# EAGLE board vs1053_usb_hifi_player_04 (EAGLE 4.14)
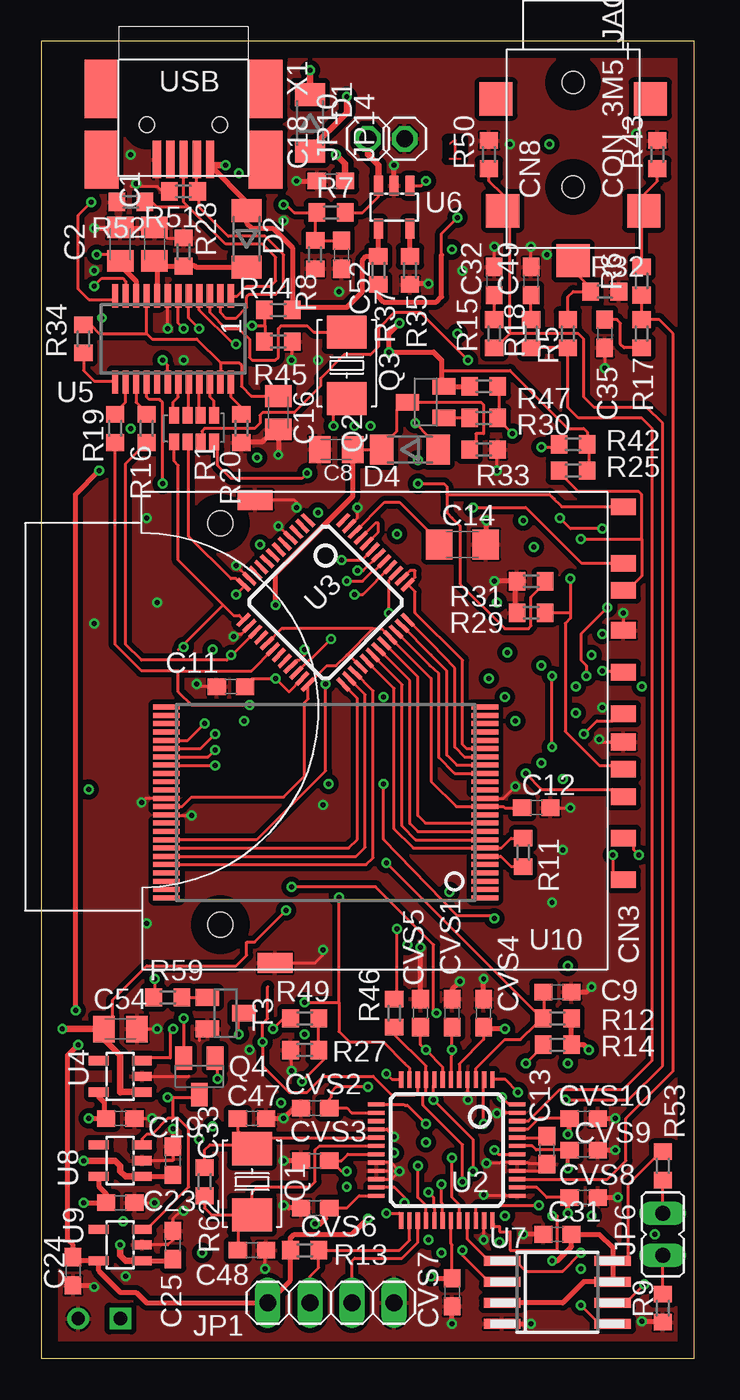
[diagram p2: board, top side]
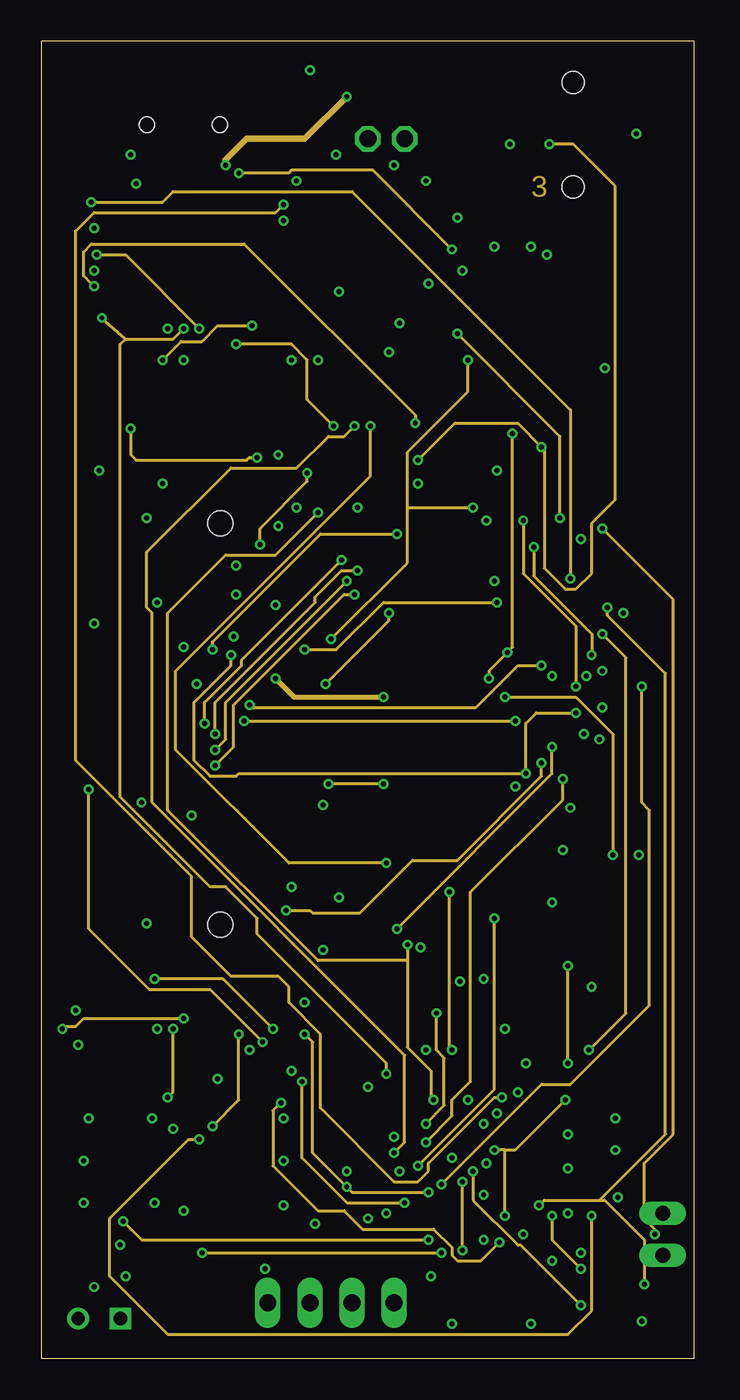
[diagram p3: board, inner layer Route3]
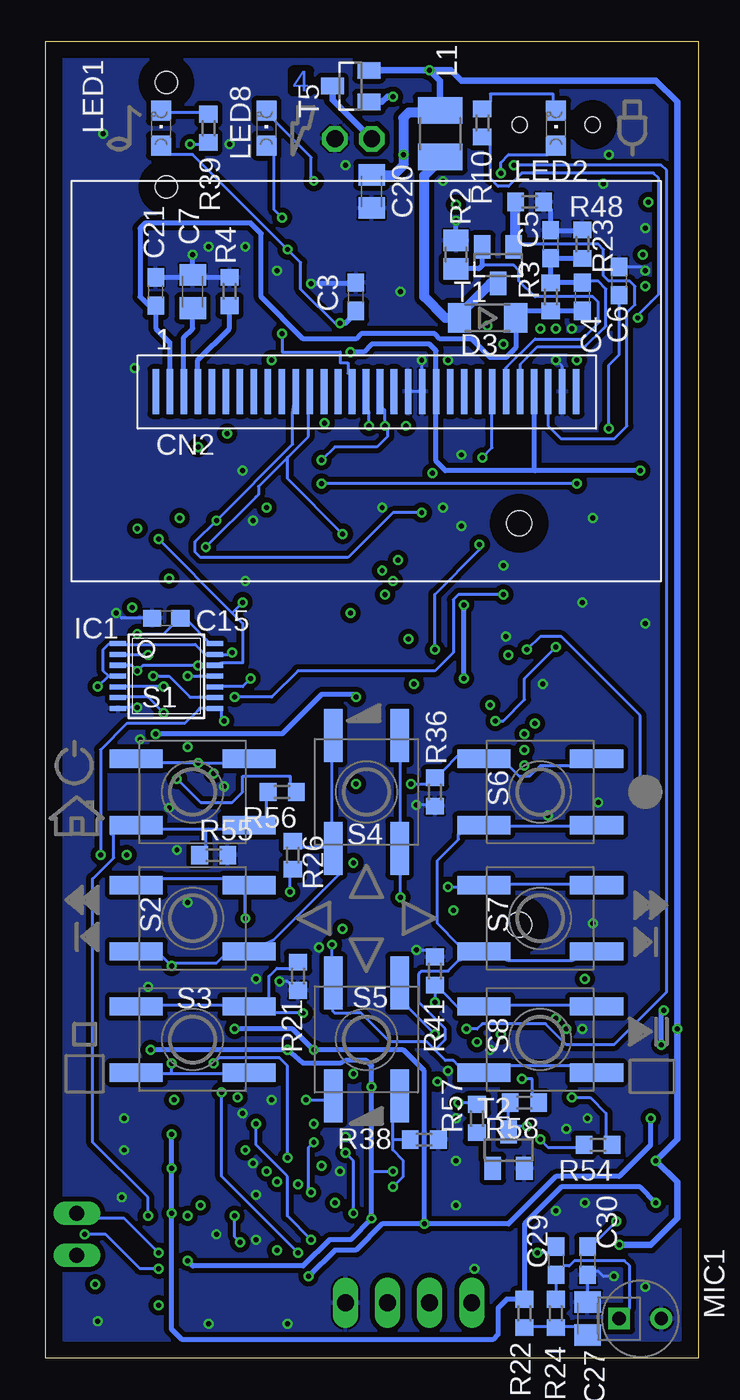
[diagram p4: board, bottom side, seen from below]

Size 39.35 x 79.36 mm. Coordinates in mm from the lower left corner, seen from the top.
Outline: 0,0 39.35,0 39.35,79.36 0,79.36 0,0
Copper layers (1*2+3*16): Top 0.0356mm / dielectric 1.5011mm / $GND 0.0356mm / dielectric 0.1499mm / Route3 0.0356mm / dielectric 0.2007mm / Bottom 0.0356mm
Design rules "oma_4layer": minimum track width 7mil, minimum drill 0.3mm, track to track 0.15mm, track to pad 8mil, pad to pad 7mil, via to via 8mil, smd to smd 7mil, copper to edge 40mil, drill to drill 8mil, minimum pad ring 10mil, minimum via ring 0.15mm, stop-mask expansion 0.1mm, vias tented up to drill 100mil, thermal gap 5mil

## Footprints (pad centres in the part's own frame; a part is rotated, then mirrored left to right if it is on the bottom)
C0805K = smd 1.3 x 1.6: 1 -1,0; 2 1,0
C0603 = smd 1.1 x 1: 1 -0.85,0; 2 0.85,0
C1206 = smd 1.6 x 1.8: 1 -1.4,0; 2 1.4,0
CON_DESITRON_OLED = smd 0.4 x 2.7: 1 0,0; 2 0.845,0; 3 1.69,0; 4 2.535,0; 5 3.38,0; 6 4.225,0; 7 5.07,0; 8 5.915,0; 9 6.76,0; 10 7.605,0; 11 8.45,0; 12 9.295,0; 13 10.14,0; 14 10.985,0; 15 11.83,0; 16 12.675,0; 17 13.52,0; 18 14.365,0; 19 15.21,0; 20 16.055,0; 21 16.9,0; 22 17.745,0; 23 18.59,0; 24 19.435,0; 25 20.28,0; 26 21.125,0; 27 21.97,0; 28 22.815,0; 29 23.66,0; 30 24.505,0; 31 25.35,0
CON_SDCARD_PROCONN = smd 1.5 x 1: 1 -24.3,21.48; 2 -24.3,18.98; 3 -24.3,16.48; 4 -24.3,14.83; 5 -24.3,13.18; 6 -24.3,11.48; 7 -24.3,8.98; 8 -24.3,6.45; 9 -24.3,4.05; 10 -24.3,2.4; 11 -24.3,-1 | smd 2.1 x 1.2: 12 -2.1,-1.4; 13 -3.3,26.51 | hole 1.5: 0,0; 0,24.2
CON_3M5_JACK_SMD = smd 2 x 2: P$1 -4.65,-3; P$2 4.65,-3; RING 4.25,-9.75; SLEEVE -4.25,-9.75; TIP 0,-12.75 | hole 1.3: 0,-2; 0,-8.3
SOD80 = smd 1.4 x 1.8: 1 -1.7,0; 2 1.7,0
TSSOP14 = smd 0.305 x 0.991: 1 -1.95,-2.918; 2 -1.3,-2.918; 3 -0.65,-2.918; 4 0,-2.918; 5 0.65,-2.918; 6 1.3,-2.918; 7 1.95,-2.918; 8 1.95,2.918; 9 1.3,2.918; 10 0.65,2.918; 11 0,2.918; 12 -0.65,2.918; 13 -1.3,2.918; 14 -1.95,2.918
1X04 = drill 1.016 long: 1 -3.81,0; 2 -1.27,0; 3 1.27,0; 4 3.81,0
JP1 = drill 0.914 long: 1 0,-1.27; 2 0,1.27
1X01 = drill 1.016 octagon: 1 0,0
R1210 = smd 1.6 x 2.7: 1 -1.4,0; 2 1.4,0
CHIPLED_0805 = smd 1.2 x 1.2: A 0,-1.05; C 0,1.05
MIC = drill 0.8 square: 1 0,1.27 | drill 0.8 round: 2 0,-1.27
CRYSTAL_5X3.2 = smd 2 x 2.4: P$1 -2,0; P$2 2,0
SOT23-BEC = smd 1 x 1.4: B -0.95,-1.1; C 0,1.1; E 0.95,-1.1
RAS_ARR_1206 = smd 1 x 0.6: 1 -0.8,1.2; 2 0.8,1.2; 3 -0.8,0.4; 4 0.8,0.4; 5 -0.8,-0.4; 6 0.8,-0.4; 7 -0.8,-1.2; 8 0.8,-1.2
R0805 = smd 1.3 x 1.5: 1 -0.85,0; 2 0.85,0
R0603 = smd 1 x 1.1: 1 -0.85,0; 2 0.85,0
SW_EVQ = smd 3.2 x 1.1: A -3.4,2; A1 3.4,2; B -3.4,-2; B1 3.4,-2
SOT23 = smd 1 x 1.4: 1 -0.95,-1.1; 2 0.95,-1.1; 3 0,1.1
LQFP48 = smd 0.25 x 1: 1 -2.75,-4.25; 2 -2.25,-4.25; 3 -1.75,-4.25; 4 -1.25,-4.25; 5 -0.75,-4.25; 6 -0.25,-4.25; 7 0.25,-4.25; 8 0.75,-4.25; 9 1.25,-4.25; 10 1.75,-4.25; 11 2.25,-4.25; 12 2.75,-4.25; 25 2.75,4.25; 26 2.25,4.25; 27 1.75,4.25; 28 1.25,4.25; 29 0.75,4.25; 30 0.25,4.25; 31 -0.25,4.25; 32 -0.75,4.25; 33 -1.25,4.25; 34 -1.75,4.25; 35 -2.25,4.25; 36 -2.75,4.25 | smd 1 x 0.25: 13 4.25,-2.75; 14 4.25,-2.25; 15 4.25,-1.75; 16 4.25,-1.25; 17 4.25,-0.75; 18 4.25,-0.25; 19 4.25,0.25; 20 4.25,0.75; 21 4.25,1.25; 22 4.25,1.75; 23 4.25,2.25; 24 4.25,2.75; 37 -4.25,2.75; 38 -4.25,2.25; 39 -4.25,1.75; 40 -4.25,1.25; 41 -4.25,0.75; 42 -4.25,0.25; 43 -4.25,-0.25; 44 -4.25,-0.75; 45 -4.25,-1.25; 46 -4.25,-1.75; 47 -4.25,-2.25; 48 -4.25,-2.75
SOT23-5L = smd 0.55 x 1.2: 1 -0.95,-1.3; 2 0,-1.3; 3 0.95,-1.3; 4 0.95,1.3; 5 -0.95,1.3
QSOP24 = smd 0.381 x 1.397: 1 -6.985,-4.5; 2 -6.35,-4.5; 3 -5.715,-4.5; 4 -5.08,-4.5; 5 -4.445,-4.5; 6 -3.81,-4.5; 7 -3.175,-4.5; 8 -2.54,-4.5; 9 -1.905,-4.5; 10 -1.27,-4.5; 11 -0.635,-4.5; 12 0,-4.5; 13 0,0.69; 14 -0.635,0.69; 15 -1.27,0.69; 16 -1.905,0.69; 17 -2.54,0.69; 18 -3.175,0.69; 19 -3.81,0.69; 20 -4.445,0.69; 21 -5.08,0.69; 22 -5.715,0.69; 23 -6.35,0.69; 24 -6.985,0.69
SO-08M = smd 0.6 x 2.2: 1 -1.905,-3.33; 2 -0.635,-3.33; 3 0.635,-3.33; 4 1.905,-3.33; 5 1.905,3.33; 6 0.635,3.33; 7 -0.635,3.33; 8 -1.905,3.33
TSOP48L = smd 1.6 x 0.3: 1 -9.6,5.75; 2 -9.6,5.25; 3 -9.6,4.75; 4 -9.6,4.25; 5 -9.6,3.75; 6 -9.6,3.25; 7 -9.6,2.75; 8 -9.6,2.25; 9 -9.6,1.75; 10 -9.6,1.25; 11 -9.6,0.75; 12 -9.6,0.25; 13 -9.6,-0.25; 14 -9.6,-0.75; 15 -9.6,-1.25; 16 -9.6,-1.75; 17 -9.6,-2.25; 18 -9.6,-2.75; 19 -9.6,-3.25; 20 -9.6,-3.75; 21 -9.6,-4.25; 22 -9.6,-4.75; 23 -9.6,-5.25; 24 -9.6,-5.75; 25 9.6,-5.75; 26 9.6,-5.25; 27 9.6,-4.75; 28 9.6,-4.25; 29 9.6,-3.75; 30 9.6,-3.25; 31 9.6,-2.75; 32 9.6,-2.25; 33 9.6,-1.75; 34 9.6,-1.25; 35 9.6,-0.75; 36 9.6,-0.25; 37 9.6,0.25; 38 9.6,0.75; 39 9.6,1.25; 40 9.6,1.75; 41 9.6,2.25; 42 9.6,2.75; 43 9.6,3.25; 44 9.6,3.75; 45 9.6,4.25; 46 9.6,4.75; 47 9.6,5.25; 48 9.6,5.75
MINI_USB_MOLEX = smd 2.25 x 0.5: 1 7.915,1.6; 2 7.915,0.8; 3 7.915,0; 4 7.915,-0.8; 5 7.915,-1.6 | smd 3.5 x 2.05: P$6 7.915,4.95; P$7 7.915,-4.95; P$8 3.665,4.95; P$9 3.665,-4.95 | hole 0.9: 5.815,2.2; 5.815,-2.2

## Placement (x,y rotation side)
C1  10u  [C0805K]  6.82,67.14 90 top
C2  10u  [C0805K]  4.76,67.14 90 top
C3  100n  [C0603]  20.63,63.97 90 bottom
C4  10n  [C0603]  6.98,63.97 90 bottom
C5  10n  [C0603]  8.88,67.14 90 bottom
C6  1u  [C0603]  4.76,64.92 90 bottom
C7  4u7/16V  [C0805K]  30.48,64.29 90 bottom
C8  10u  [C0805K]  17.78,54.76 180 top
C9  100n  [C0603]  31.11,22.06 0 top
C11  100n  [C0603]  11.42,40.48 180 top
C12  100n  [C0603]  29.84,33.17 0 top
C13  1u  [C0603]  30.48,12.54 270 top
C14  10u  [C1206]  25.4,49.05 0 top
C15  100n  [C0603]  32.06,44.6 180 bottom
C16  10u  [C0805K]  14.28,56.98 270 top
C18  1u  [C0603]  17.46,70.95 180 top
C19  1u  [C0603]  4.76,14.44 0 top
C20  10u  [C0805K]  19.68,70.32 270 bottom
C21  1u  [C0603]  32.7,64.29 90 bottom
C23  1u  [C0603]  4.76,9.36 0 top
C24  1u  [C0603]  1.9,5.23 270 top
C25  1u  [C0603]  7.93,6.82 90 top
C27  10u  [C0805K]  6.66,2.38 90 bottom
C29  100n  [C0603]  8.57,5.87 270 bottom
C30  100n  [C0603]  6.66,5.87 270 bottom
C31  100n  [C0603]  31.11,7.46 0 top
C32  47n  [C0603]  27.3,64.92 90 top
C33  1u  [C0603]  7.93,11.9 90 top
C35  10n  [C0603]  33.97,61.75 270 top
C47  22p  [C0603]  12.7,14.44 0 top
C48  22p  [C0603]  12.7,6.5 0 top
C49  10n  [C0603]  29.52,64.92 90 top
C52  1u  [C0603]  18.09,66.51 270 top
C54  10u  [C0805K]  4.76,19.84 0 top
CN2  CON_DESITRON_OLED_SSD1303  [CON_DESITRON_OLED]  32.7,58.25 0 bottom
CN3  CON_SDCARD_PROCON  [CON_SDCARD_PROCONN]  10.79,50.32 180 top
CN8  CON_3M5_JACK  [CON_3M5_JACK_SMD]  32.06,78.89 0 top
CVS1  100n  [C0603]  24.76,20.79 90 top
CVS2  100n  [C0603]  16.5,15.08 180 top
CVS3  100n  [C0603]  16.5,11.9 180 top
CVS4  100n  [C0603]  26.67,20.79 90 top
CVS5  100n  [C0603]  22.86,20.79 90 top
CVS6  100n  [C0603]  16.5,9.04 180 top
CVS7  100n  [C0603]  24.76,3.96 270 top
CVS8  100n  [C0603]  32.7,9.68 0 top
CVS9  100n  [C0603]  32.7,12.54 0 top
CVS10  100n  [C0603]  32.7,14.44 0 top
D1  BAS85  [SOD80]  16.19,74.45 270 top
D2  BAS85  [SOD80]  12.38,67.46 90 top
D3  BAS85  [SOD80]  12.7,62.7 180 bottom
D4  BAS85  [SOD80]  22.22,54.76 0 top
IC1  74AC125  [TSSOP14]  32.06,41.11 270 bottom
JP1  [1X04]  17.46,3.33 0 top
JP6  #SPIBOOT  [JP1]  37.46,7.46 0 top
JP10  [1X01]  19.68,73.5 90 top
JP14  [1X01]  21.9,73.5 90 top
L1  10u  [R1210]  15.55,73.81 270 bottom
LED1  [CHIPLED_0805]  32.38,74.13 0 bottom
LED2  [CHIPLED_0805]  8.57,74.13 0 bottom
LED8  [CHIPLED_0805]  26.03,74.13 0 bottom
MIC1  MIC  [MIC]  3.49,2.38 90 bottom
Q1  12.288MHz  [CRYSTAL_5X3.2]  12.7,10.63 270 top
Q2  [CRYSTAL_5X3.2]  18.41,59.84 90 top
Q3  BC858ASMD  [SOT23-BEC]  23.17,57.62 90 top
Q4  BC858ASMD  [SOT23-BEC]  9.52,16.98 180 top
R1  100  [RAS_ARR_1206]  9.2,56.03 90 top
R2  1.2  [R0805]  14.6,66.51 270 bottom
R3  470k  [R0603]  8.88,63.97 270 bottom
R4  1M  [R0603]  28.25,64.29 270 bottom
R5  10  [R0603]  31.75,61.75 90 top
R6  10  [R0603]  36.19,64.92 90 top
R7  470k  [R0603]  17.46,69.05 0 top
R8  470k  [R0603]  16.5,66.51 90 top
R9  10k  [R0603]  37.46,3.01 90 top
R10  1k  [R0603]  13.01,74.45 270 bottom
R11  0  [R0603]  29.05,30.47 270 top
R12  100k  [R0603]  31.11,20.47 0 top
R13  100k  [R0603]  15.87,6.5 180 top
R14  100k  [R0603]  31.11,18.88 0 top
R15  10  [R0603]  27.3,61.75 270 top
R16  100  [R0603]  6.34,56.03 270 top
R17  20  [R0603]  36.19,61.75 90 top
R18  20  [R0603]  29.52,61.75 270 top
R19  100  [R0603]  4.44,56.03 270 top
R20  330  [R0603]  12.06,56.03 270 top
R21  100k  [R0603]  24.12,23.01 90 bottom
R22  1k  [R0603]  10.47,2.69 90 bottom
R23  68k  [R0603]  6.98,67.14 270 bottom
R24  2.2k  [R0603]  8.57,2.69 270 bottom
R25  100k  [R0603]  32.06,53.49 0 top
R26  10k  [R0603]  24.44,30.31 270 bottom
R27  100k  [R0603]  15.87,18.57 0 top
R28  10k  [R0603]  8.57,66.67 90 top
R29  ZERO  [R0603]  29.52,44.92 180 top
R30  4k7  [R0603]  26.67,56.67 180 top
R31  ZERO  [R0603]  29.52,46.82 180 top
R32  CG060MLA-5.5M  [R0603]  33.97,64.29 0 top
R33  1k  [R0603]  26.67,54.76 180 top
R34  100k  [R0603]  2.54,61.43 270 top
R35  10k  [R0603]  22.22,65.56 90 top
R36  100k  [R0603]  15.87,34.12 90 bottom
R37  10k  [R0603]  20.32,65.56 90 top
R38  100k  [R0603]  16.5,13.17 180 bottom
R39  1k  [R0603]  29.52,74.13 90 bottom
R41  100k  [R0603]  15.87,23.33 270 bottom
R42  100k  [R0603]  32.06,55.08 0 top
R43  CG060MLA-5.5M  [R0603]  37.14,72.54 90 top
R44  47k  [R0603]  14.28,63.18 180 top
R45  100k  [R0603]  14.28,61.27 0 top
R46  330  [R0603]  21.27,20.79 270 top
R47  100k  [R0603]  26.67,58.57 180 top
R48  1M  [R0603]  10.15,69.69 180 bottom
R49  47k  [R0603]  15.87,20.47 180 top
R50  CG060MLA-5.5M  [R0603]  26.98,72.54 90 top
R51  CG060MLA-5.5M  [R0603]  8.57,70.32 180 top
R52  CG060MLA-5.5M  [R0603]  5.39,69.69 180 top
R53  100k  [R0603]  37.46,11.58 90 top
R54  10k  [R0603]  6.03,12.85 180 bottom
R55  1k  [R0603]  29.21,30.31 0 bottom
R56  10k  [R0603]  25.08,34.12 180 bottom
R57  10k  [R0603]  13.33,14.44 90 bottom
R58  10k  [R0603]  10.47,15.39 180 bottom
R59  10k  [R0603]  7.62,21.74 180 top
R62  1Meg  [R0603]  9.84,10.63 270 top
S1  [SW_EVQ]  30.48,34.12 0 bottom
S2  [SW_EVQ]  30.48,26.5 180 bottom
S3  [SW_EVQ]  30.48,19.2 180 bottom
S4  [SW_EVQ]  20,34.12 90 bottom
S5  [SW_EVQ]  20,19.2 90 bottom
S6  [SW_EVQ]  9.52,34.12 180 bottom
S7  [SW_EVQ]  9.52,26.5 180 bottom
S8  [SW_EVQ]  9.52,19.2 180 bottom
T1  SI2302ADS  [SOT23]  12.06,65.88 180 bottom
T2  BC848  [SOT23]  11.42,12.54 0 bottom
T3  BC848  [SOT23]  11.11,20.79 270 top
T5  SI2315DS  [SOT23]  20.95,76.67 90 bottom
U2  VS1053-L  [LQFP48]  24.44,12.54 180 top
U3  CBM3082  [LQFP48]  17.14,45.55 225 top
U4  1.8V  [SOT23-5L]  4.76,16.98 90 top
U5  CBM4082  [QSOP24]  4.44,59.52 180 top
U6  LTC4054  [SOT23-5L]  21.27,69.37 180 top
U7  W25X16  [SO-08M]  31.11,3.96 270 top
U8  3.3V  [SOT23-5L]  4.76,11.9 90 top
U9  3.3V  [SOT23-5L]  4.76,6.82 90 top
U10  NAND_FLASH_2CS  [TSOP48L]  17.14,33.49 180 top
X1  [MINI_USB_MOLEX]  8.57,80.16 270 top

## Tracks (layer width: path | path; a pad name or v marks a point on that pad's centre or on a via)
3V3  (via drill 0.3)
  Top 0.178: 24.76,19.84 24.69,19.77 | U2.14 18.7,14.79 18.41,15.08 CVS2.1 17.35,15.61 17.46,15.71 17.46,16.03 17.78,16.34 v19.68,16.34 | U2.19 18.48,12.29 18.09,11.9 17.46,11.9 | U2.6 24.69,18.18 24.76,18.25 v24.76,18.57 24.76,19.84 | 24.76,19.84 CVS1.1 | v18.41,11.27 18.09,11.27 17.46,11.9 | 17.46,11.9 CVS3.1 | 24.12,59.52 28.25,59.52 31.59,56.19 31.75,56.03 32.7,56.03 32.91,55.82 R42.2 33.02,54.6 33.02,53.97 R25.2 | R53.2 36.98,12.06 35.4,10.47 35.4,6.03 U7.8
  Top 0.305: 3.49,5.87 U9.5 | U9.5 3.46,5.26 4.76,3.96 5.71,3.96 6.34,3.33 JP1.1 15.02,4.7 R13.2 15.02,7.24 15.23,7.46 18.73,7.46 v19.68,8.41 | R12.2 31.96,18.99 32.06,18.88 R14.2 32.7,18.88 v33.02,18.57 | 1.9,6.18 1.9,6.82 1.58,7.14 1.58,18.25 v2.22,18.88 | v2.06,20.95 2.06,52.06 v3.49,53.49 | 24.12,59.52 24.12,60.16 23.65,60.64 v20.95,60.64 20.95,61.75 v21.58,62.38 | 24.12,59.52 24.13,59.52 | 24.12,59.52 24.12,58.57 24.13,58.57 Q3.E 26.03,58.57 R47.2 | v30.79,5.87 31.11,5.87 31.96,6.72 C31.2 33.65,7.46 34.44,6.67 U7.8 34.28,5.87 34.44,5.71 U7.7 32.7,4.6 31.43,3.33 U7.3 | 1.9,6.18 C24.1 | U9.5 2.22,5.87 1.9,6.18
  Route3 0.178: v24.6,28.09 24.6,18.73 v24.76,18.57 | v33.81,43.65 35.24,42.22 35.24,20.79 33.17,18.73 v33.02,18.57 | v11.9,71.43 14.92,71.43 15.08,71.59 20,71.59 v24.76,66.83
  Bottom 0.178: 19.68,11.27 v18.41,11.27 | v24.6,28.09 24.6,29.04 R26.2 | IC1.14 29.52,43.17 30.79,44.44 C15.1 31.75,44.13 32.22,43.65 v33.81,43.65 | LED1.A 31.9,72.54 30.48,72.54 v24.76,66.83 23.97,66.03 23.97,64.45 21.74,62.22 v21.58,62.38 | v11.9,71.43 11.9,72.07 11.43,72.54 9.04,72.54 LED2.A
  Bottom 0.305: v33.02,18.57 v24.76,18.57 23.81,17.77 21.58,17.77 21.27,17.93 20,17.93 19.68,17.61 v19.68,16.34 19.68,11.27 v19.68,8.41 20.95,7.14 22.22,7.14 23.81,5.55 30.47,5.55 v30.79,5.87 | 9.84,53.49 15.23,53.49 15.8,54.05 CN2.21 15.8,60.72 16.19,61.11 19.68,61.11 20.16,60.64 v20.95,60.64 | C3.1 20.63,63.02 21.27,62.38 v21.58,62.38 | v3.49,53.49 9.84,53.49 | CN2.28 9.88,53.54 9.84,53.49 | v2.06,20.95 | v2.22,18.88 2.22,20.79 v2.06,20.95
4D0
  Top 0.178: R1.8 10.4,57.69 10.15,57.94 U5.22
4D1
  Top 0.178: R1.6 9.6,56.9 9.52,56.98 U5.21
4D2
  Top 0.178: R1.4 8.8,56.9 8.89,56.98 U5.20
4D3
  Top 0.178: U5.19 8.25,57.94 7.93,57.62 7.93,56.98 8,56.91 R1.2
4SD_CLK
  Top 0.178: R19.1 4.44,56.98 5.08,57.62 U5.14
4SD_CMD
  Top 0.178: R16.1 6.34,56.98 5.71,57.62 U5.15
AVDDM  (via drill 0.3)
  Top 0.178: 31.74,9.68 30.47,9.68 29.87,10.29 U2.38 | U2.43 29.59,12.79 29.84,12.54 CVS9.1 | CVS10.1 30,14.44 29.34,13.79 U2.45
  Top 0.254: CVS9.1 31.74,12.43 v31.74,11.42
  Top 0.305: U8.5 3.49,10.95 3.49,10.31 3.91,9.89 C23.1 v2.53,9.36 | CVS8.1 31.74,9.68 v31.74,8.73 | CVS10.1 31.85,13.59 v31.74,13.49
  Bottom 0.305: v31.74,13.49 v31.74,11.42 v31.74,8.73 31.74,1.74 31.11,1.1 12.38,1.1 12.06,1.42 12.06,3.01 11.53,3.54 R22.2 10.47,8.09 8.25,10.31 3.49,10.31 v2.53,9.36
CBUF  (via drill 0.3)
  Top 0.178: U2.42 27.55,12.29 v27.3,12.54 | v31.59,15.55 35.4,15.55 37.46,17.61 37.46,56.35 36.51,57.3 33.33,57.3 32.7,57.94 32.7,61.43 32.38,61.75 28.25,61.75 | R15.2 27.3,60.8 28.25,61.75 | 28.25,61.75 28.25,68.41 27.81,68.86 CN8.SLEEVE 27.81,70.12 26.98,70.95 R50.1
  Route3 0.178: 27.94,12.54 v27.3,12.54 | 27.94,12.54 28.57,12.54 v31.59,15.55 | v14.44,15.39 13.97,14.92 13.97,11.58 16.66,8.88 18.25,8.88 19.36,7.77 23.65,7.77 24.76,6.66 24.76,6.18 25.08,5.87 26.51,5.87 v27.62,6.98 | v27.94,8.57 27.94,12.54 | 27.94,12.54
  Bottom 0.178: v14.44,15.39 13.81,15.39 R57.2 | v27.62,6.98 27.94,7.3 v27.94,8.57
CVDD  (via drill 0.3)
  Top 0.178: U2.7 24.19,17.55 v23.17,18.57 22.85,18.88 CVS5.1 | U2.5 25.19,17.73 26.67,19.2 26.67,19.84 | 17.14,9.04 CVS6.1 18.41,9.04 19.15,9.79 U2.24 | CVS7.1 24.76,6.82 24.69,6.89 U2.31
  Top 0.305: U4.5 3.46,15.74 3.8,15.39 3.8,14.44 C19.1 v2.85,14.44 | CVS7.1 23.59,4.81 v23.49,4.92 | v16.5,8.09 16.82,8.09 17.14,8.41 17.14,9.04 | CVS4.1 26.67,19.84 v27.94,19.84
  Bottom 0.305: v2.85,14.44 2.85,12.85 4.76,10.95 8.57,10.95 11.42,8.09 v16.5,8.09 | v16.5,8.09 19.05,8.09 20.63,6.5 21.9,6.5 v23.49,4.92 | v16.5,8.09 16.5,17.3 17.78,18.57 v23.17,18.57 24.44,19.84 v27.94,19.84
FB
  Bottom 0.178: R23.2 7.19,66.3 7.3,66.19 7.4,66.3 | C4.2 7.19,64.82 7.3,64.92 7.4,64.82 | CN2.27 10.73,59.91 9.68,60.95 6.82,60.95 5.71,62.06 5.55,62.22 5.55,64.45 6.03,64.92 6.88,64.92 C4.2 | C4.2 6.56,64.82
  Bottom 0.305: 7.4,66.3 C5.1 R3.1 7.4,64.82
GDR
  Bottom 0.178: 11.11,67.14 11,67.25 | 11.11,67.14 T1.1 | 11.11,67.14 6.03,67.14 5.71,66.83 5.71,65.24 5.39,64.92 4.12,64.92 3.8,64.61 3.8,63.49 4.28,63.02 4.28,56.19 5.08,55.4 8.25,55.4 9.04,56.19 CN2.29
  Bottom 0.305: R48.2 11.11,69.69 11,69.58
  Bottom 0.61: 11,67.25 11,69.58
GND  (via drill 0.3)
  Top 0.178: C2.2 5.55,68.1 | 6.19,68.1 C1.2 | R20.2 12.54,55.24 | U2.40 29.05,11.27 30,11.27 C13.2 30,11.74 29.36,11.74 29.32,11.79 U2.41 27.66,11.79 27.62,11.74 | U2.21 20.63,11.27 v21.59,11.27 v21.58,11.27 | v25.71,15.55 25.71,16.34 U2.4 | v14.28,50.16 14.6,49.84 U3.4 | 7.93,8.09 | 7.93,8.09 7.93,8.41 8.41,8.88 v8.57,8.88 | 7.93,8.09 C25.2 7.93,7.14 7.62,6.82 6.5,6.82 U9.2 | v6.82,9.36 6.03,9.36 C23.2 | v7.93,13.81 7.93,13.17 C33.2 7.93,12.22 7.93,11.9 6.5,11.9 U8.2 | v6.66,14.44 6.03,14.44 C19.2 | v13.49,5.39 13.49,6.03 C48.2 | CVS6.2 15.24,9.04 | C47.2 13.97,14.44 | CVS3.2 15.24,11.9 | 24.76,2.69 CVS7.2 | v15.08,17.3 15.08,18.09 R27.1 | C31.1 29.84,7.46 | 36.98,2.22 R9.1 | CVS8.2 33.97,9.68 | CVS5.2 22.86,22.06 | CVS9.2 33.97,12.54 | CVS10.2 33.97,14.44 | 24.76,22.06 CVS1.2 | CVS4.2 26.67,22.06 | v9.36,40.63 9.52,40.48 10.15,40.48 C11.2 | C9.2 32.38,22.06 | v15.08,60.16 15.08,61.59 R45.2 | v27.46,53.49 27.46,54.29 R33.1 | 22.7,64.76 R35.1 | 16.19,70.95 C18.2 | v27.3,66.99 27.3,66.19 C32.2 | v33.97,59.68 33.97,60.48 C35.2 | v29.52,66.99 29.52,66.19 C49.2 | 8.89,16.98 6.5,16.98 U4.2 | U6.2 21.27,71.11 | v7.62,62.06 7.62,63.34 U5.7 | v6.98,19.84 6.35,19.84 C54.2 | v9.04,32.7 8.25,32.7 U10.38 | 27.62,11.74 v26.82,11.74 | U7.4 28.73,2.06 | U2.20 21.06,11.79 v21.58,11.27 | U2.22 21.1,10.79 v21.58,11.27 | U3.14 12.06,43.65 11.74,43.65 v11.58,43.49 | U3.11 v11.74,47.78 | U3.47 19.05,50.63 v19.05,51.27 | U2.16 20.81,13.79 v21.27,13.33 | U10.36 6.28,33.74 v6.03,33.49 | U10.13 27.87,33.74 v28.57,34.44 | v26.67,7.14 | U2.35 26.69,7.17 v26.67,7.14 | v27.46,14.76 27.49,14.79 U2.47 | 27.62,11.74 | v26.67,9.84 | U2.37 26.72,9.79 v26.67,9.84 | v31.9,33.17 31.11,33.17 C12.2
  Top 0.178: v33.65,37.3 33.65,37.14 34.44,37.14 CN3.5 | CN3.8 35.08,44.28 v35.08,44.92 | CN3.13 15.08,23.81 16.51,23.81 17.14,24.44 v16.98,24.6 | v15.39,51.27 15.39,51.59 15.24,51.75 13.81,51.75 CN3.12 | R28.2 7.56,67.52 6.98,68.1 | R51.2 7.3,70.32 6.98,70.64 5.39,70.64 | 5.39,70.64 | v5.71,70.8 5.39,70.64 | 9.52,19.12 9.52,19.36 T3.2
  Top 0.305: 5.55,68.1 6.19,68.1 | 12.54,55.24 13.33,55.24 13.49,55.4 C16.2 v14.28,54.45 | 15.24,9.04 15.23,9.04 14.92,9.04 v14.6,9.2 | 13.97,14.44 v14.6,14.44 | 15.24,11.9 v14.6,11.9 | v24.76,2.06 24.76,2.69 | 29.84,7.46 v29.05,7.46 | v36.19,2.22 36.98,2.22 | 33.97,9.68 v34.76,9.68 | 22.86,22.06 v22.86,24.76 | 33.97,12.54 v34.6,12.54 | 33.97,14.44 v34.6,14.44 | 24.76,22.06 24.76,22.22 25.08,22.54 v25.24,22.7 | 26.67,22.06 v26.67,22.85 | 32.38,22.06 32.86,22.06 v33.17,22.38 | v23.33,64.76 22.7,64.76 | v15.39,70.95 16.19,70.95 | 21.27,71.11 v21.27,71.91 | 28.73,2.06 v29.52,2.06 | v3.17,68.1 3.96,68.1 C2.2 | C24.2 3.07,4.38 v3.17,4.28 | CVS2.2 15.34,15.18 v14.6,14.44 | v14.6,14.44 | v26.82,50.48 26.82,49.84 C14.2 | 28.57,46.82 v27.3,46.82 | 28.57,46.82 R31.2 | R29.2 28.57,44.92 28.57,46.82
  Bottom 0.178: R23.1 7.46,67.94 | 8.41,67.94 C5.2 8.89,68.41 | C27.2 6.66,3.96 6.66,4.6 C30.2 6.19,5.23 6.03,5.23 5.71,4.92 v5.08,4.92 | v16.98,24.6 16.35,24.6 R41.1 | v16.98,33.33 16.35,33.33 R36.1 | v25.24,22.7 24.76,22.7 24.6,22.54 R21.1 | C3.2 21.11,64.76 | R2.1 14.6,67.94 | v16.66,60.16 16.66,59.52 CN2.20 16.82,58.25 17.3,58.25 CN2.19 | C6.2 3.39,65.77 v3.17,65.56 | CN2.30 8.19,59.78 v8.57,60.16 | v33.81,39.2 34.6,39.2 IC1.7 | v35.08,44.92 34.76,44.6 33.33,44.6 C15.2
  Bottom 0.305: 7.46,67.94 8.41,67.94 | 8.89,68.41 8.89,69.21 | 21.11,64.76 v23.33,64.76 | 14.6,67.94 v14.6,68.57 | R4.1 30.37,65.14 30.47,65.24 | 30.47,65.24 C7.2 v30.47,66.51 | C21.2 30.58,65.14 30.47,65.24
  other vias: 17.93,64.29 6.34,50.63 6.98,45.55 3.17,44.28 6.34,26.19 30.79,27.46 31.43,30.63 28.25,73.18 25.4,65.56 35.87,73.81 5.39,72.54 12.54,18.57
  pour Top (isolate 0.305): -0.32,79.84 39.68,79.84 39.68,-0.17 -0.32,-0.17
  pour Bottom (isolate 0.305): -0.01,79.53 39.68,79.53 39.68,-0.17 -0.01,-0.17
GPIO6  (via drill 0.3)
  Top 0.178: 21.9,17.77 20.63,19.04 18.57,19.04 17.93,19.68 17.93,21.42 | 17.93,21.42 v17.93,27.77 | v15.87,21.42 17.93,21.42 | 21.9,17.77 | U2.11 22.19,17.48 21.9,17.77
  Bottom 0.178: S8.B 7.62,21.27 11.43,21.27 S8.B1 14.44,21.11 15.39,22.06 R41.2 15.87,22.06 v15.87,21.42 | v17.93,27.77 17.93,29.2 S4.B 17.93,32.22 17.93,36.03 S4.B1
GPIO7/XLED  (via drill 0.3)
  Top 0.178: v8.57,62.06 8.25,62.38 8.25,63.34 U5.6 | U2.12 21.15,16.79 v20.79,17.14
  Route3 0.178: v20.79,17.14 20.79,17.77 18.57,20 18.41,20.15 13.01,25.55 13.01,26.5 11.11,28.41 10.16,28.41 4.76,33.81 4.76,61.11 5.08,61.43 | v8.57,62.06 7.93,61.43 5.08,61.43 | 5.08,61.43 v3.65,62.7
  Bottom 0.178: v3.65,62.7 3.65,62.86 2.85,63.65 2.38,64.13 2.38,70.95 | R10.2 12.54,73.18 12.54,71.11 12.06,70.64 11.42,70.64 10.63,71.43 2.69,71.43 2.38,71.11 2.38,70.95 | 2.38,70.95 | 2.38,70.95
LCD_RS  (via drill 0.3)
  Top 0.178: v30.79,8.57 31.11,8.57 31.11,6.5 28.25,6.5 28.25,7.61 27.62,7.61 27.62,7.93 27.3,7.93 U2.36 | v33.81,50 31.9,50 v31.27,50.63
  Route3 0.178: v30.79,8.57 30.79,7.14 v32.54,5.39 | v36.98,7.46 36.98,7.77 36.35,8.41 36.35,11.74 38.1,13.49 38.1,45.71 v33.81,50 | v31.27,50.63 31.27,55.56 v25.08,61.75
  Bottom 0.178: v32.54,5.39 33.65,5.39 35.71,7.46 v36.98,7.46 | v25.08,61.75 25.08,60.64 21.59,60.64 21.59,60 21.11,60 21.11,59.37 20.95,59.21 CN2.15
LCD_XCS  (via drill 0.3)
  Top 0.178: v30.16,54.92 30.79,54.92 R42.1 | v20.79,8.73 21.59,8.73 U2.25
  Route3 0.178: v30.63,73.18 32.06,73.18 34.6,70.64 34.6,51.75 33.17,50.32 33.17,47.3 32.22,46.35 31.59,46.35 30.32,47.62 30.32,54.76 v30.16,54.92 28.73,56.35 24.92,56.35 v22.7,54.13 | v21.27,12.38 21.9,13.01 21.9,18.25 6.66,33.49 6.66,44.92 6.35,45.24 6.35,48.57 11.43,53.65 15.39,53.65 17.3,55.56 18.25,55.56 v18.89,56.19
  Bottom 0.178: v30.63,73.18 30,73.18 R39.1 | v20.79,8.73 20.79,11.9 v21.27,12.38 | CN2.17 19.05,57.3 18.89,57.14 v18.89,56.19 18.73,56.03 18.73,55.56 19.36,54.92 21.9,54.92 v22.7,54.13
LEFT
  Top 0.178: U2.46 29.37,14.29 31.27,16.19 35.08,16.19 36.82,17.93 36.82,56.03 36.19,56.67 32.38,56.67 31.74,57.3 R5.1 29.62,60.9 29.52,60.8 R18.2
LR  (via drill 0.3)
  Top 0.178: v27.78,15.71 | U2.48 28.2,15.29 v27.78,15.71 | C52.1 16.61,67.36 16.5,67.46 R8.2 16.5,69.05 R7.1 15.24,69.05 14.76,69.53 v14.6,69.53
  Route3 0.178: v27.78,15.71 27.3,15.71 23.33,11.74 23.33,11.27 22.7,10.63 21.27,10.63 16.82,15.08 16.82,19.52 | 16.82,19.52 | 16.82,19.52 14.92,21.42 14.92,22.38 14.28,23.01 11.42,23.01 9.04,25.39 9.04,29.04 2.06,36.03 2.06,67.94 3.17,69.05 14.12,69.05 v14.6,69.53
MICN  (via drill 0.3)
  Top 0.178: v26.67,14.12 26.67,16.34 U2.2
  Route3 0.178: v23.33,7.14 6.03,7.14 v4.92,8.25
  Bottom 0.178: v26.67,14.12 26.67,12.85 24.76,10.95 24.76,8.57 v23.33,7.14 | v4.92,8.25 6.19,6.98 C30.1
MICP  (via drill 0.3)
  Top 0.178: v28.73,16.03 28.41,16.34 | U2.1 27.97,16.79 v28.73,16.03 | v28.73,16.03
  Route3 0.178: v9.68,6.34 v24.13,6.34
  Bottom 0.178: v28.73,16.03 28.73,10.95 v24.13,6.34 | v9.68,6.34 9.04,6.34 C29.1
N$1
  Top 0.178: U10.10 23.15,32.24 22.7,32.7 22.7,41.06 U3.32
N$2  (via drill 0.3)
  Top 0.178: U10.29 8.83,37.24 v9.84,38.25 | U3.43 19.33,48.09 v18.09,48.09
  Route3 0.178: v9.84,38.25 9.84,39.52 12.06,41.74 12.06,42.06 v18.09,48.09
N$3
  Top 0.178: 36.42,69.14 36.51,69.05 36.19,68.73 R6.2 | 36.42,69.14 CN8.RING | 36.42,69.14 36.42,70.23 37.14,70.95 R43.1
N$4
  Top 0.178: CN8.TIP 32.06,65.88 31.74,65.56 | CN8.TIP 32.06,66.19 | CN8.TIP 32.06,65.56 33.12,64.5 R32.1 32.06,64.29 31.74,63.97 R5.2
N$5  (via drill 0.3)
  Top 0.178: U3.42 19.4,47.46 v19.05,47.46 | U10.30 9.6,36.74 v10.47,37.62
  Route3 0.178: v19.05,47.46 18.09,47.46 16.5,45.87 16.5,45.55 10.47,39.52 v10.47,37.62
N$6
  Bottom 0.305: CN2.3 31.01,61.53 30.47,62.06 C7.1
N$7  (via drill 0.3)
  Top 0.178: U10.31 10.05,36.24 v10.47,36.66 | v18.41,46.82 19.36,46.82 20,47.46 20.11,47.46 U3.41
  Route3 0.178: v10.47,36.66 11.11,37.3 11.11,39.52 v18.41,46.82
N$8  (via drill 0.3)
  Top 0.178: U3.40 19.38,46.03 v18.89,46.03 | U10.32 7.57,35.71 v10.47,35.71
  Route3 0.178: v18.89,46.03 18.25,46.03 11.58,39.36 11.58,36.82 v10.47,35.71
N$9  (via drill 0.3)
  Route3 0.178: v31.75,17.77 v31.75,23.65
  Bottom 0.178: 31.75,17.14 32.38,17.14 S3.A1 | 31.75,17.14 28.57,17.14 S3.A | S2.A 28.57,24.92 | 31.75,17.14 v31.75,17.77 | 32.38,24.28 v31.75,23.65 31.59,23.81 29.05,23.81 28.57,24.28 S2.A | S4.A 22.54,30.79 23.97,30.79 R26.1 | S4.A1 22.06,36.03 22.06,32.22 S4.A | S2.A 25.55,25.23 21.59,29.2 S4.A | 32.38,24.28 S2.A1 | 32.38,24.28
N$10  (via drill 0.3)
  Top 0.178: v20.95,44.92 20.95,46.67 | v17.14,40.63 17.14,35.39 13.01,31.27 8.25,31.27 U10.41 | 20.95,46.67 | U3.39 20.95,46.89 20.95,46.67
  Route3 0.178: v20.95,44.92 20.95,44.44 v17.14,40.63
N$11
  Bottom 0.178: C27.1 7.46,1.9 8.09,1.9 R24.2 9.04,1.9 10,1.9 R22.1
N$12
  Top 0.178: U10.42 18.52,30.74 19.05,31.27 19.05,39.76 U3.25
N$13
  Bottom 0.178: R10.1 12.54,75.72 12.54,76.19 8.73,76.19 8.73,75.72 LED2.C
N$14
  Top 0.178: U10.43 18.97,30.24 19.52,30.79 19.52,39.99 U3.26
N$15
  Top 0.178: U10.44 19.58,29.74 20,30.16 20,40.22 U3.27
N$16
  Top 0.178: U10.9 22.7,31.74 22.22,32.22 22.22,40.83 U3.31
N$17
  Bottom 0.178: R24.1 8.57,3.96 8.57,4.6 C29.2 8.09,5.55 7.77,5.55 7.46,5.87 4.44,5.87 4.12,5.55 4.12,3.01 MIC1.1
N$18
  Top 0.178: U3.29 21.27,40.37 21.27,31.9 22.43,30.74 U10.7 27.72,30.74 28.31,31.32 R11.1
N$19
  Top 0.178: R9.2 37.46,4.28 37.46,5.55 JP6.1
N$20
  Bottom 0.305: D3.2 14.39,62.91 | 12.53,64.78 T1.3
  Bottom 0.61: D3.2 15.23,62.7 16.5,63.97 16.5,71.27 15.87,71.91 L1.2 | 14.39,62.91 12.53,64.78
N$21
  Top 0.178: U10.8 22.56,31.24 21.74,32.06 21.74,40.6 U3.30
N$22
  Top 0.178: U10.18 25.5,36.24 24.92,36.82 24.92,41.59 23.57,43.02 U3.36
N$23
  Top 0.178: U10.16 24.92,35.24 23.97,36.19 23.97,41.27 23.42,41.74 U3.34
N$24
  Top 0.178: U10.17 25.05,35.74 24.44,36.35 24.44,41.43 23.5,42.38 U3.35
N$25
  Top 0.178: U3.45 20.13,50.32 20.31,50.32 20.31,49.79 U3.44
N$26  (via drill 0.3)
  Top 0.178: v21.43,25.87 21.43,22.06 R46.1 | v30.79,36.82 v30.79,41.11
  Route3 0.178: v30.79,36.82 30.79,35.24 21.59,26.03 v21.43,25.87
  Bottom 0.178: v30.79,41.11 IC1.11
N$27
  Top 0.178: R30.2 25.4,56.67 24.92,56.67 Q3.B
N$28
  Top 0.178: U5.1 11.8,64.03 12.38,64.61 13.81,64.61 14.12,64.92 14.12,66.35 13.33,67.14 11.11,67.14 8.89,69.37 | X1.3 8.57,69.69 8.89,69.37 | R52.1 6.66,69.69 6.98,69.37 8.89,69.37
N$29  (via drill 0.3)
  Route3 0.178: v9.52,13.17 8.89,13.17 4.12,8.41 4.12,4.92 7.62,1.42 31.75,1.42 33.17,2.85 v33.17,8.57
  Bottom 0.178: R56.2 26.03,33.65 26.03,32.54 S1.B1 28.57,31.9 29.52,31.9 | 29.52,31.9 29.68,31.74 29.68,30.79 R55.1 | 29.52,31.9 32.38,31.9 S1.B 35.4,31.58 35.24,31.9 35.24,30.16 36.51,28.89 36.51,13.01 33.17,9.68 v33.17,8.57 | v9.52,13.17 9.04,12.69 7.3,12.69 R54.2
N$30
  Top 0.178: C14.1 23.33,49.84 21.59,51.59 21.58,51.59 20.7,51.59 U3.46
N$32
  Top 0.178: R34.2 2.53,59.52 3.17,58.89 4.44,58.89 U5.13
N$33
  Top 0.178: 10.79,60 U5.23 | 10.79,60 11.9,60 | 10.79,60 9.36,61.43 6.66,61.43 6.34,61.75 | 6.34,61.75 U5.9 | R34.1 2.95,62.28 3.49,61.75 6.34,61.75 | C16.1 12.65,57.98 12.06,58.57 12.06,59.84 11.9,60 | 11.9,60
N$34
  Top 0.305: D2.1 9.31,65.76 9.2,65.88 R28.1 7.35,65.82 6.98,66.19 6.93,66.14 C1.1 6.71,66.14 | 6.71,66.14 6.66,66.19 | U5.8 6.98,65.88 6.71,66.14
N$36
  Top 0.305: U6.5 22.22,68.09 22.22,68.1 R35.2
N$37  (via drill 0.3)
  Top 0.178: 24.12,66.51 24.12,67.78 v25.08,68.73
  Top 0.305: R37.1 20.31,63.97 20.63,63.65 23.81,63.65 24.12,63.97 24.12,66.51
  Bottom 0.178: LED8.A 25.55,72.54 25.55,69.21 v25.08,68.73
N$38
  Top 0.178: U10.19 25.64,36.74 25.4,36.98 25.4,42.06 22.54,44.92 22.54,46.19 22.11,46.62 U3.37 22.54,47.06 22.54,47.46 22.23,47.46 U3.38
N$39
  Top 0.178: Q2.P$2 16.41,61.84 16.03,62.22 14.44,62.22 14.28,62.06 14.28,60.32 14.12,60.16 12.7,60.16 12.54,60.32 12.54,61.43 11.9,62.06 11.11,62.06 10.15,63.02 U5.3
N$40  (via drill 0.3)
  Top 0.178: v11.74,61.11 11.58,61.11 9.52,63.18 9.52,63.34 U5.4 | v17.62,56.19 17.62,56.98 Q2.P$1
  Route3 0.178: v11.74,61.11 15.08,61.11 16.03,60.16 16.03,57.78 v17.62,56.19
N$41
  Top 0.178: U5.24 11.42,57.94 12.06,57.3 R20.1
N$42  (via drill 0.3)
  Top 0.178: v10.63,16.82 10.63,17.46 Q4.B
  Bottom 0.178: v10.63,16.82 10,16.82 10,15.87 R58.1
N$43
  Top 0.178: U5.2 10.79,63.02 11.11,62.7 11.74,62.7 12.38,63.34 12.38,63.97 12.54,64.13 14.12,64.13 14.6,64.61 14.6,66.51 13.49,67.62 11.27,67.62 10.95,67.94 9.52,69.37 9.52,70.32 | X1.2 9.37,70.47 9.52,70.32 | 9.52,70.32 R51.1
N$44
  Bottom 0.178: R39.2 30,75.08 31.9,75.08 LED1.C
N$45  (via drill 0.3)
  Top 0.178: v11.9,19.52 11.9,20.31 T3.3
  Route3 0.178: v11.9,19.52 11.9,15.55 v10.31,13.96
  Bottom 0.178: R58.2 11.43,14.92 11.43,14.28 T2.3 10.95,13.96 v10.31,13.96
N$46  (via drill 0.3)
  Top 0.178: 4.76,65.88 C2.1 3.96,66.51 v3.33,66.51 | v9.52,62.06 8.89,62.7 8.89,63.34 U5.5
  Top 0.305: U5.10 5.71,64.92 4.76,65.88
  Route3 0.178: v9.52,62.06 5.08,66.51 v3.33,66.51
N$47  (via drill 0.3)
  Top 0.178: v24.76,12.06 24.76,9.68 25.19,9.25 U2.32 | v29.21,17.77 29.84,18.41 R14.1
  Bottom 0.178: v24.76,12.06 24.76,17.61 25.24,18.09 28.89,18.09 v29.21,17.77
N$48
  Bottom 0.178: R57.1 12.85,13.17 12.85,12.06 T2.1
N$49
  Top 0.178: R15.1 C32.1
N$50
  Top 0.178: R17.1 35.14,60.9 34.92,61.11 34.92,62.38 34.71,62.6 C35.1
N$51
  Top 0.178: R18.1 C49.1
N$52  (via drill 0.3)
  Top 0.178: U9.3 6.34,7.77 8.89,10.31 8.89,13.81 8.25,14.44 7.93,14.44 | U8.3 6.06,13.2 6.34,13.49 6.66,13.49 7.62,14.44 7.93,14.44 | 7.93,15.71 9.04,15.71 Q4.C | 7.93,15.71 v7.62,15.71 | v7.93,19.84 7.77,19.84 7.77,18.09 6.5,18.09 U4.3 | 7.93,14.44 7.93,15.71 | 7.93,14.44
  Route3 0.178: v7.93,19.84 7.93,16.03 v7.62,15.71
  Bottom 0.178: v7.62,15.71 6.5,15.71 5.55,14.76 5.55,13.33 R54.1
N$53
  Bottom 0.305: CN2.4 30.16,60.16 28.25,62.06 R4.2
N$54  (via drill 0.3)
  Top 0.178: 13.49,62.22 13.49,62.86 R44.2 | 13.49,62.22 13.49,61.91 R45.1 | v7.3,60.16 7.62,59.84 7.62,59.52 U5.18 | v12.7,62.22 13.49,62.22
  Route3 0.178: v7.3,60.16 8.41,61.27 9.68,61.27 10.63,62.22 v12.7,62.22
N$55
  Top 0.178: R59.1 8.89,21.74 9.36,21.74 T3.1
NF_VCC
  Top 0.178: U10.37 8.48,33.24 9.04,33.81 14.6,33.81 15.87,35.08 15.87,39.52 16.08,39.73 U3.24 17.22,41.74 17.78,41.74 18.41,42.38 | U3.17 14.49,43.97 14.6,43.97 | U3.28 18.55,42.38 18.41,42.38 | 20,43.97 20.5,43.97 U3.33 23.49,40.97 23.49,34.76 25.01,33.24 U10.12 27.87,33.24 27.94,33.17 C12.1 | 18.41,42.38 20,43.97 | 20,43.97 14.6,43.97 | 14.6,43.97 | 20,43.97
OLED_VCC
  Bottom 0.178: 8.78,63.12 8.89,63.02 | D3.1 11.11,62.7 10.69,63.12
  Bottom 0.254: 33.02,63.34 32.7,63.34
  Bottom 0.305: CN2.2 31.85,61.22 32.7,62.06 32.7,63.34 C21.1 | C4.1 8.78,63.12 | D3.1 10.99,60.91 11.58,60.32 12.54,60.32 13.65,61.43 15.55,61.43 15.87,61.75 20.31,61.75 20.63,61.43 23.81,61.43 26.35,63.97 26.35,67.78 26.98,68.41 33.33,68.41 33.65,68.1 33.65,63.97 33.02,63.34 | R3.2 8.89,63.02 8.99,63.12 10.69,63.12
R/B2
  Top 0.178: U10.6 27.69,30.24 28.31,29.62 R11.2
RCAP
  Top 0.178: C13.1 30.47,13.49 30.27,13.29 U2.44
RESE
  Bottom 0.178: 13.01,66.83 T1.2 | CN2.26 11.57,59.7 9.84,61.43 6.98,61.43 6.03,62.38 6.03,63.65 6.34,63.97 9.84,63.97 10.79,64.92 10.79,65.56 11.11,65.88 13.01,65.88
  Bottom 0.305: R2.2 13.23,65.66 13.01,65.88 13.01,66.83
RIGHT
  Top 0.178: U2.39 34.12,10.79 35.24,11.9 35.24,14.44 38.1,17.3 38.1,61.75 37.24,62.6 R17.2 R6.1
SD_#ON  (via drill 0.3)
  Top 0.178: R47.1 27.62,58.1 27.62,57.14 R30.1 27.94,56.19 v28.41,55.71 | v24.13,10.47 24.13,9.36 24.12,9.36 24.19,9.29 U2.30
  Route3 0.178: v26.98,40.95 26.98,41.43 v28.09,42.54 28.41,42.86 v28.41,55.71 | v24.13,10.47 30.16,16.5 31.9,16.5 36.67,21.27 36.67,33.01 36.19,33.49 v36.19,40.48
  Bottom 0.178: v26.98,40.95 27.46,40.48 28.73,40.48 IC1.10 | IC1.13 29.52,42.38 | IC1.13 28.22,42.41 v28.09,42.54 | 35.56,41.11 35.87,41.43 35.87,42.7 35.51,43.06 IC1.1 34.6,43.02 30.32,43.02 29.84,42.54 29.71,42.41 IC1.13 | 35.56,41.11 IC1.4 | v36.19,40.48 35.56,41.11
SD_CD  (via drill 0.3)
  Top 0.178: v3.01,69.69 2.22,68.89 2.22,64.45 2.85,63.81 4.28,63.81 U5.12 | v31.9,46.98 31.9,44.92 | 31.9,44.92 31.9,44.6 31.59,44.28 31.59,37.78 33.65,35.71 34.44,35.71 CN3.4 | 31.9,44.92 30.79,44.92 R29.1
  Route3 0.178: v3.01,69.69 7.3,69.69 7.93,70.32 18.73,70.32 31.9,57.14 v31.9,46.98
SD_CLK  (via drill 0.3)
  Top 0.178: R19.2 4.44,43.02 6.03,41.43 8.25,41.43 | U3.18 12.66,41.43 8.25,41.43 | v12.54,39.36 9.04,39.36 8.25,40.16 8.25,41.43 | v33.81,41.43 34.44,41.43 CN3.7
  Route3 0.178: v30.16,41.74 28.73,41.74 26.19,39.2 12.7,39.2 v12.54,39.36
  Bottom 0.178: IC1.3 34.6,41.74 34.13,41.74 v33.81,41.43 33.49,41.74 v30.16,41.74
SD_CMD/SD_SI  (via drill 0.3)
  Top 0.178: R16.2 5.08,53.91 5.08,43.02 6.03,42.06 11.17,42.06 11.46,42.35 | 11.46,42.35 U3.15 | v11.43,42.38 11.46,42.35 | v29.21,35.24 30.16,34.28 34.44,34.28 CN3.3
  Route3 0.178: v11.43,42.38 11.43,41.74 9.2,39.52 9.2,36.03 10.16,35.08 11.74,35.08 11.9,35.24 v29.21,35.24 29.21,38.25 29.84,38.89 v32.22,38.89
  Bottom 0.178: v32.22,38.89 33.17,39.84 34.6,39.84 IC1.6
SD_D0/SD_SO  (via drill 0.3)
  Top 0.178: 36.19,49.37 36.19,47.14 35.71,46.67 CN3.9 | 36.19,49.37 36.19,52.06 36.03,52.22 32.38,52.22 31.59,53.02 R25.1 | v32.54,49.37 36.19,49.37 | v15.87,42.7 15.87,42.38 15.55,42.06 15.39,42.06 U3.21 | v16.03,53.33 15.71,53.02 11.43,53.02 10.63,53.81 10.63,54.76 R1.7
  Route3 0.178: v15.87,42.7 17.78,42.7 20.63,45.55 v27.46,45.55 | v16.03,53.33 16.03,52.86 13.17,50 v13.17,49.05
  Bottom 0.178: 29.52,41.74 IC1.12 28.73,41.9 27.46,41.9 27.46,44.28 28.09,44.92 | 28.09,44.92 v32.54,49.37 | v27.46,45.55 28.09,44.92 | v13.17,49.05 13.17,48.73 15.87,46.03 v15.87,42.7
SD_D1  (via drill 0.3)
  Top 0.178: v25.71,60.16 22.86,63.02 21.27,63.02 20.32,62.06 20.32,60.95 19.84,60.48 18.25,60.48 16.82,59.05 16.82,58.57 15.24,56.98 13.33,56.98 13.17,56.83 13.17,56.35 12.85,56.03 9.84,56.03 9.68,55.87 9.68,55.71 R1.5 | U3.22 16.12,42.06 16.19,42.06 v17.46,43.33 | 32.06,48.41 29.21,51.27 v26.03,51.27 | 32.06,48.41 | CN3.10 32.56,47.92 32.06,48.41
  Route3 0.178: v25.71,60.16 25.71,58.25 22.06,54.6 22.06,51.27 | v17.46,43.33 22.06,47.94 22.06,51.27 | 22.06,51.27 v26.03,51.27
SD_D2  (via drill 0.3)
  Top 0.178: R1.3 8.89,54.76 8.89,49.52 11.43,46.98 11.74,46.98 U3.12 12.22,46.51 v11.74,46.03 | v34.44,30.31 34.44,29.2 CN3.1
  Route3 0.178: v34.44,30.31 34.44,37.62 32.22,39.84 v27.94,39.84
  Bottom 0.178: v27.94,39.84 25.71,39.84 24.13,41.43 15.87,41.43 14.76,42.54 14.76,45.71 14.44,46.03 v11.74,46.03
SD_D3/SD_XCS  (via drill 0.3)
  Top 0.178: R1.1 8,54.06 8.25,53.81 8.25,48.09 10.95,45.4 | 8.41,42.86 8.25,42.7 | 8.41,42.86 10.95,45.4 | 10.95,45.4 | 10.95,45.4 11.58,44.76 11.92,44.76 U3.13 | v36.03,30.31 35.71,30.63 35.71,31.74 CN3.2 | v8.57,42.86 8.41,42.86
  Route3 0.178: v12.22,38.41 v28.57,38.41
  Bottom 0.178: v36.03,30.31 36.03,36.66 34.44,38.25 30.95,38.25 30.16,39.05 | 30.16,39.05 | 30.16,39.05 30.04,39.16 IC1.8 28.73,39.05 28.73,38.41 v28.57,38.41 | v12.22,38.41 11.74,38.41 10.47,39.68 10.47,40.95 v8.57,42.86
SD_VCC  (via drill 0.3)
  Top 0.178: D4.1 21.11,55.56 21.43,55.87 21.43,57.14 Q3.C 22.7,57.62 26.51,57.62 26.67,57.46 26.67,55.71 26.19,55.71 26.19,55.24 R33.2 | C11.1 12.7,40.95 v14.12,40.95 14.28,40.79 14.92,40.16 U3.23 | v32.7,37.62 33.49,38.41 34.44,38.41 CN3.6 | D4.1 20.63,54.76 | C8.1 D4.1
  Top 0.305: v14.12,45.4 14.12,47.3 18.78,51.95 C8.1
  Route3 0.178: v14.12,40.95 14.28,40.79
  Route3 0.305: v20.63,39.84 15.24,39.84 14.28,40.79
  Bottom 0.178: v20.63,39.84 20.79,40
  Bottom 0.305: v14.12,40.95 v14.12,45.4 | v32.7,37.62 25.08,37.62 22.7,40 20.79,40
SD_WP  (via drill 0.3)
  Top 0.178: 30.79,51.91 30.63,52.06 24.44,52.06 | 30.79,51.91 30.95,51.75 | R31.1 30,46.35 29.52,45.87 29.52,44.13 29.36,43.97 27.94,43.97 25.24,46.67 25.24,50.16 24.76,50.63 24.44,50.95 24.44,52.06 | v7.3,52.7 7.3,57.62 7.14,57.78 6.5,57.78 6.35,57.94 6.35,58.25 U5.16 | v22.7,52.7 24.28,52.7 24.44,52.54 24.44,52.06 | 30.79,51.91 | CN3.11 31.38,51.32 30.79,51.91
  Bottom 0.178: v7.3,52.7 v22.7,52.7
SW_CLK/SD_CLK  (via drill 0.3)
  Top 0.178: 13.65,22.38 13.65,20.47 13.33,20.15 v13.33,19.04 | v13.33,19.04 13.33,17.61 14.92,16.03 16.03,16.03 16.98,16.98 20,16.98 21.11,15.87 22.54,15.87 22.7,16.03 22.7,16.34 U2.10 | v13.33,19.04
  Route3 0.178: v33.17,42.38 33.17,43.65 29.68,47.14 v29.68,48.89 | v13.33,19.04 10.16,22.22 6.5,22.22 2.85,25.87 v2.85,34.28 | v10.31,42.7 10.31,43.17 16.82,49.68 v21.43,49.68
  Bottom 0.178: 24.76,54.29 26.51,52.54 26.51,52.06 26.67,51.91 | 24.76,54.29 23.49,55.56 23.49,56.98 CN2.12 | v33.17,42.38 34.6,42.38 IC1.2 | 26.67,51.91 v29.68,48.89 | 26.67,51.91 | 26.67,51.91 | v2.85,34.28 3.49,34.92 3.49,38.73 8.25,43.49 9.52,43.49 v10.31,42.7 | v21.43,49.68 24.76,53.02 24.76,54.29
SW_EE_XCS  (via drill 0.3)
  Top 0.178: R53.1 37.46,10.31 37.46,9.36 JP6.2 | 25.71,7.14 26.82,6.03 U7.1 28.73,5.71 29.21,5.23 31.43,5.23 v32.54,6.34 | 25.71,7.14 | U2.33 25.69,7.16 25.71,7.14
  Bottom 0.178: v32.54,6.34 34.6,8.41 37.14,8.41 JP6.2
SW_SD_XCS  (via drill 0.3)
  Top 0.178: v36.35,4.44 35.4,3.49 U7.6 | v30,9.2 26.35,9.2 26.19,9.04 26.19,8.73 U2.34 | v32.86,41.11 32.86,41.74 32.54,42.06 32.54,43.65 v34.13,45.24
  Route3 0.178: v36.35,4.44 36.35,7.14 33.97,9.52 33.65,9.52 | v30,9.2 30.32,9.52 33.65,9.52 | v34.13,45.24 34.13,44.76 37.62,41.27 37.62,13.49 33.65,9.52
  Bottom 0.178: v32.86,41.11 31.9,41.11 30.63,39.84 29.52,39.84 IC1.9
SW_SI/SD_SO  (via drill 0.3)
  Top 0.178: 23.17,17.61 21.27,19.52 R46.2 | v25.4,6.5 25.4,6.18 26.82,4.76 U7.2 | v25.4,10.63 25.4,12.85 23.01,15.23 23.01,15.87 23.17,16.03 23.17,16.34 U2.9 23.19,17.59 23.17,17.61 | 23.17,17.61
  Route3 0.178: v25.4,6.5 v25.4,10.63
SW_SO/SD_CMD  (via drill 0.3)
  Top 0.178: U2.8 23.65,16.34 v23.65,15.55 23.81,15.39 26.03,13.17 v26.03,11.27 | v32.54,3.17 33.49,2.22 U7.5
  Route3 0.178: v32.54,3.17 28.89,6.82 28.73,6.82 26.03,9.52 v26.03,11.27 | v22.06,24.92 22.06,23.96 | 22.06,23.96 22.06,18.73 23.49,17.3 23.49,15.71 v23.65,15.55 | v32.22,40.48 32.22,44.13 29.05,47.3 v29.05,50.48 | 22.06,23.96 16.66,23.96 7.62,33.01 7.62,44.92 11.11,48.41 14.12,48.41 v16.66,50.95
  Bottom 0.178: v23.65,15.55 22.54,15.55 S5.A | S8.A 7.62,17.61 11.43,17.61 S8.A1 14.44,17.61 14.76,17.93 15.24,17.93 15.87,18.57 | 20.95,20.79 20.32,20.79 18.57,19.04 16.35,19.04 15.87,18.57 | S6.A 7.62,32.06 11.43,32.06 S6.A1 14.44,31.58 14.44,31.27 15.71,30 15.71,26.19 14.44,24.92 S7.A1 | S7.A 7.62,23.96 11.43,23.96 S7.A1 | 15.87,18.57 15.24,19.2 15.24,19.84 16.82,21.42 16.82,23.17 16.66,23.33 15.08,23.33 14.44,23.96 S7.A1 | v22.06,24.92 22.06,23.81 S5.A1 22,20.88 21.9,20.79 20.95,20.79 | v32.22,40.48 34.6,40.48 IC1.5 | CN2.11 24.44,56.98 24.44,55.08 v29.05,50.48 30.32,49.21 30.32,48.57 30,48.25 21.11,48.25 18.41,50.95 v16.66,50.95 | 20.95,20.79
VBAT
  Top 0.178: R7.2 19.36,69.05 20.31,70 20.31,70.64 20.32,70.64 U6.3
  Top 0.406: JP10.1 19.68,72.54 20.31,71.91 20.31,70.95 20.32,70.95 U6.3
  Bottom 0.406: T5.3 22.05,75.86 JP10.1
VBREF  (via drill 0.3)
  Route3 0.178: v13.01,54.29 12.54,54.29 12.38,54.13 5.71,54.13 5.39,54.45 v5.39,56.03
  Bottom 0.178: C6.1 4.76,60.48 5.39,59.84 5.39,56.67 v5.39,56.03 | CN2.25 12.42,54.88 v13.01,54.29
VBUS  (via drill 0.3)
  Top 0.178: R49.2 14.6,20.47 v13.97,19.84 | X1.1 10.17,72.24 10.15,72.22 10.47,71.91 | v6.82,22.85 6.82,22.22 R59.2
  Top 0.305: X1.1 10.17,71.89 12.38,69.69 D2.2 12.38,68.41 12.7,68.1 13.97,68.1 15.13,66.93 R44.1 15.55,63.34 18.41,63.34 19.36,64.29 19.36,66.19 19.58,66.41 R37.2 20.31,66.51 20.32,66.51 U6.4
  Top 0.406: v11.11,71.91 10.47,71.91 | D1.2 16.19,72.86 18.41,75.08 v18.41,76.03
  Route3 0.178: v6.82,22.85 10.95,22.85 13.81,20 v13.97,19.84
  Route3 0.406: v11.11,71.91 11.11,72.22 12.38,73.5 15.87,73.5 v18.41,76.03
  Bottom 0.178: v13.97,19.84 13.33,19.84 13.01,20.15 9.2,20.15 7.93,18.88 5.08,18.88 1.9,22.06 1.9,71.59 2.22,71.91 v11.11,71.91
  Bottom 0.406: v18.41,76.03 18.73,76.03 19.05,75.72 20,75.72 19.99,75.72 T5.1
VBUS_DET  (via drill 0.3)
  Top 0.178: R49.1 16.72,18.67 16.82,18.57 R27.2 17.14,18.09 v15.71,16.66 | v21.9,9.36 21.9,9.68 21.3,10.29 U2.23
  Route3 0.178: v21.9,9.36 18.41,9.36 15.71,12.06 v15.71,16.66
VCC  (via drill 0.3)
  Top 0.178: U9.1 6.34,5.87 | U9.1 | 6.03,5.87 U9.1 | v8.57,20.47 8.57,18.73 Q4.E | v14.76,26.98 12.85,25.08 12.38,25.08 12.38,24.28 11.74,23.65 6.35,23.65 4.28,21.58 4.28,20.63 C54.1
  Top 0.305: C33.1 7.93,10.95 U8.1 | C25.1 7.93,5.87 U9.1
  Top 0.406: v1.27,19.84 C54.1 3.76,19.25 4.76,18.25 4.76,16.03 U4.1 | U8.1 5.07,10.95 4.76,11.27 4.76,11.58 4.44,11.9 v2.53,11.9 | v4.76,6.82 4.76,6.18 5.08,5.87 6.03,5.87 | v16.19,77.62 D1.1 | C18.1 18.31,72.01 v17.78,72.54
  Route3 0.178: v30.16,35.87 30.16,35.08 25.08,30 22.38,30 19.2,26.82 16.35,26.82 16.19,26.98 v14.76,26.98 | v8.57,20.47 2.54,20.47 2.06,20 1.42,20 v1.27,19.84
  Bottom 0.178: S1.A1 28.57,35.87 v30.16,35.87 32.38,35.87 S1.A
  Bottom 0.406: v4.76,6.82 2.85,6.82 1.27,8.41 1.27,10.63 v2.53,11.9 1.27,13.17 v1.27,19.84 1.27,75.72 2.53,76.99 14.28,76.99 14.91,77.62 v16.19,77.62 | v16.19,77.62 T5.2 | v16.19,77.62 15.55,76.99 L1.1
  Bottom 0.61: L1.1 15.87,75.08 17.46,75.08 17.78,74.77 v17.78,72.54 17.78,71.91 18.41,71.27 19.68,71.27 C20.1
VD33C  (via drill 0.3)
  Top 0.178: v3.17,64.61 3.65,65.08 4.92,65.08 5.08,64.92 5.08,64.61 U5.11 | v22.54,56.35 23.33,55.56 D4.2
  Route3 0.178: v3.17,64.61 3.01,64.76 2.54,65.24 2.54,66.67 3.01,67.14 12.22,67.14 22.54,56.83 v22.54,56.35
VS_RX
  Top 0.178: JP1.2 16.19,4.92 16.72,5.45 R13.1 21.58,6.5 22.19,7.11 U2.26
VS_SCLK  (via drill 0.3)
  Top 0.178: v22.7,11.58 22.7,9.68 23.17,9.2 23.17,8.73 U2.28 | v20.63,34.6 20.63,31.27 25.08,26.66 27.14,26.66 v27.3,26.5
  Route3 0.178: v22.7,11.58 27.3,16.19 v27.3,26.5 | v20.63,34.6 v17.3,34.6
  Bottom 0.178: S6.B 7.62,35.71 9.52,35.71 10.16,35.08 10.79,35.08 11.43,35.71 S6.B1 14.44,36.35 15.39,35.39 R36.2 16.35,34.6 v17.3,34.6 | v27.3,26.5 27.3,28.41 S2.B 28.57,28.89 32.38,28.89 S2.B1
VS_SI  (via drill 0.3)
  Top 0.178: v23.33,10 23.65,9.68 23.65,9.04 23.69,9 U2.29
  Route3 0.178: v23.33,10 18.73,10 v18.41,10.31 18.25,10.47 16.35,12.38 16.35,19.04 v15.87,19.52 | v31.43,34.92 31.43,33.65 25.87,28.09 25.87,16.66 24.76,15.55 24.76,14.6 v23.17,13.01
  Bottom 0.178: v18.41,10.31 17.78,10.95 17.78,11.9 18.41,12.54 18.41,13.17 | 18.41,13.17 18.41,14.44 S5.B | v15.87,19.52 17.46,21.11 S5.B1 | 18.41,13.17 17.78,13.17 R38.2 | 18.41,13.17 | v31.43,34.92 30,33.49 28.09,33.49 27.46,34.12 27.46,35.08 24.6,35.08 24.6,34.6 R56.1 | v23.17,13.01 23.49,12.69 23.49,10.15 v23.33,10
VS_TX
  Top 0.178: U2.27 22.69,6.97 21.74,6.03 18.89,6.03 18.73,5.87 JP1.3
VS_XDCS  (via drill 0.3)
  Top 0.178: v23.17,14.12 22.06,15.23 21.9,15.23 21.85,15.29 U2.13 | v15.08,28.41 20.16,28.41 23.65,24.92 23.65,20.95 v23.81,20.79
  Route3 0.178: v23.17,14.12 24.28,15.23 24.28,18.09 23.81,18.57 v23.81,20.79
  Bottom 0.178: S7.B 7.62,28.57 11.43,28.57 S7.B1 14.44,28.41 v15.08,28.41 | v23.81,20.79 25.55,20.79 S3.B | R21.2 24.6,23.49 25.4,23.49 25.87,23.01 25.87,21.74 S3.B | S3.B1 32.38,21.27 28.57,21.27 S3.B
VS_XRST  (via drill 0.3)
  Top 0.178: U2.3 26.19,17.14 26.19,17.46 27.94,19.2 28.89,19.2 29.84,20.15 R12.1 | C9.1 30.32,21.58 30.32,20.95 R12.1 | v20.79,29.84 29.84,20.79 R12.1
  Route3 0.178: v19.84,56.19 19.84,53.17 8.09,41.43 8.09,36.66 14.92,29.84 v20.79,29.84
  Bottom 0.178: v19.84,56.19 19.84,56.98 CN2.16
VS_XTALI
  Top 0.178: U2.18 16.75,12.79 16.5,12.54 16.5,10.63 16.19,10.31 13.01,10.31 12.7,10 12.7,8.73 | Q1.P$2 12.7,8.41 | R62.2 9.84,9.04 10.25,8.63 Q1.P$2 | Q1.P$2 12.7,8.73 | C48.1 11.85,7.88 12.7,8.73
VS_XTALO
  Top 0.178: Q1.P$1 12.7,12.54 13.45,13.29 U2.17 | Q1.P$1 12.7,12.85 11.85,13.7 C47.1 | R62.1 9.84,12.54 10.15,12.85 12.06,12.85 12.38,12.54 12.47,12.63 Q1.P$1
XCHG  (via drill 0.3)
  Top 0.178: U6.1 22.89,70.67 v23.17,70.95
  Bottom 0.178: LED8.C 25.55,74.61 23.33,72.38 23.33,71.11 v23.17,70.95

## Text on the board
Top: 1
$GND: 2
Route3: 3
Bottom: 4
tDocu: VLSI2009 | VS1053 USB HiFi Player 0.4
bDocu: MP3 WMA AAC OGG WAV FLAC MIDI | VS1053 | + | OK | C | - | R | T | + | -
